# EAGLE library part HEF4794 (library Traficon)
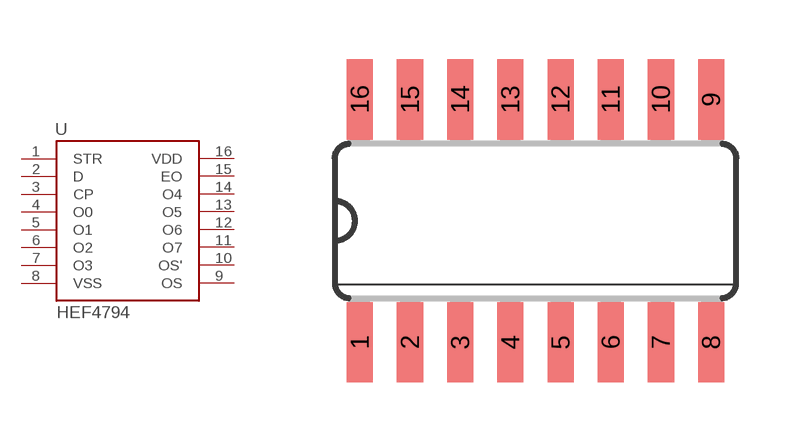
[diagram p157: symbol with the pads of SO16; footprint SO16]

Designator prefix U

## HEF4794  [SO16]
1  STR  in
2  D  in
3  CP  in
4  O0  out
5  O1  out
6  O2  out
7  O3  out
8  VSS  pwr
9  OS  out
10  OS'  out
11  O7  out
12  O6  out
13  O5  out
14  O4  out
15  EO  in
16  VDD  pwr

## Footprint SO16 (pad centres in mm)
Small Outline package 150 mil
smd 0.66 x 2.032: 1 -4.445,-3.073; 2 -3.175,-3.073; 3 -1.905,-3.073; 4 -0.635,-3.073; 5 0.635,-3.073; 6 1.905,-3.073; 7 3.175,-3.073; 8 4.445,-3.073; 9 4.445,3.073; 10 3.175,3.073; 11 1.905,3.073; 12 0.635,3.073; 13 -0.635,3.073; 14 -1.905,3.073; 15 -3.175,3.073; 16 -4.445,3.073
